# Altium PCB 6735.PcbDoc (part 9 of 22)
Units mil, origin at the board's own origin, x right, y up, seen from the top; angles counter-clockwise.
Board outline 2641.73 x 5165.35 mil, 6 copper layers (Top, Inner Layer 2, Inner Layer 3, Inner Layer 4, Inner Layer 5, Bottom), stack 35.7 mil thick; 1011 components, 790 nets, 4118 pads, 9325 vias.
Unrouted connection lines stored in the file: 4610.
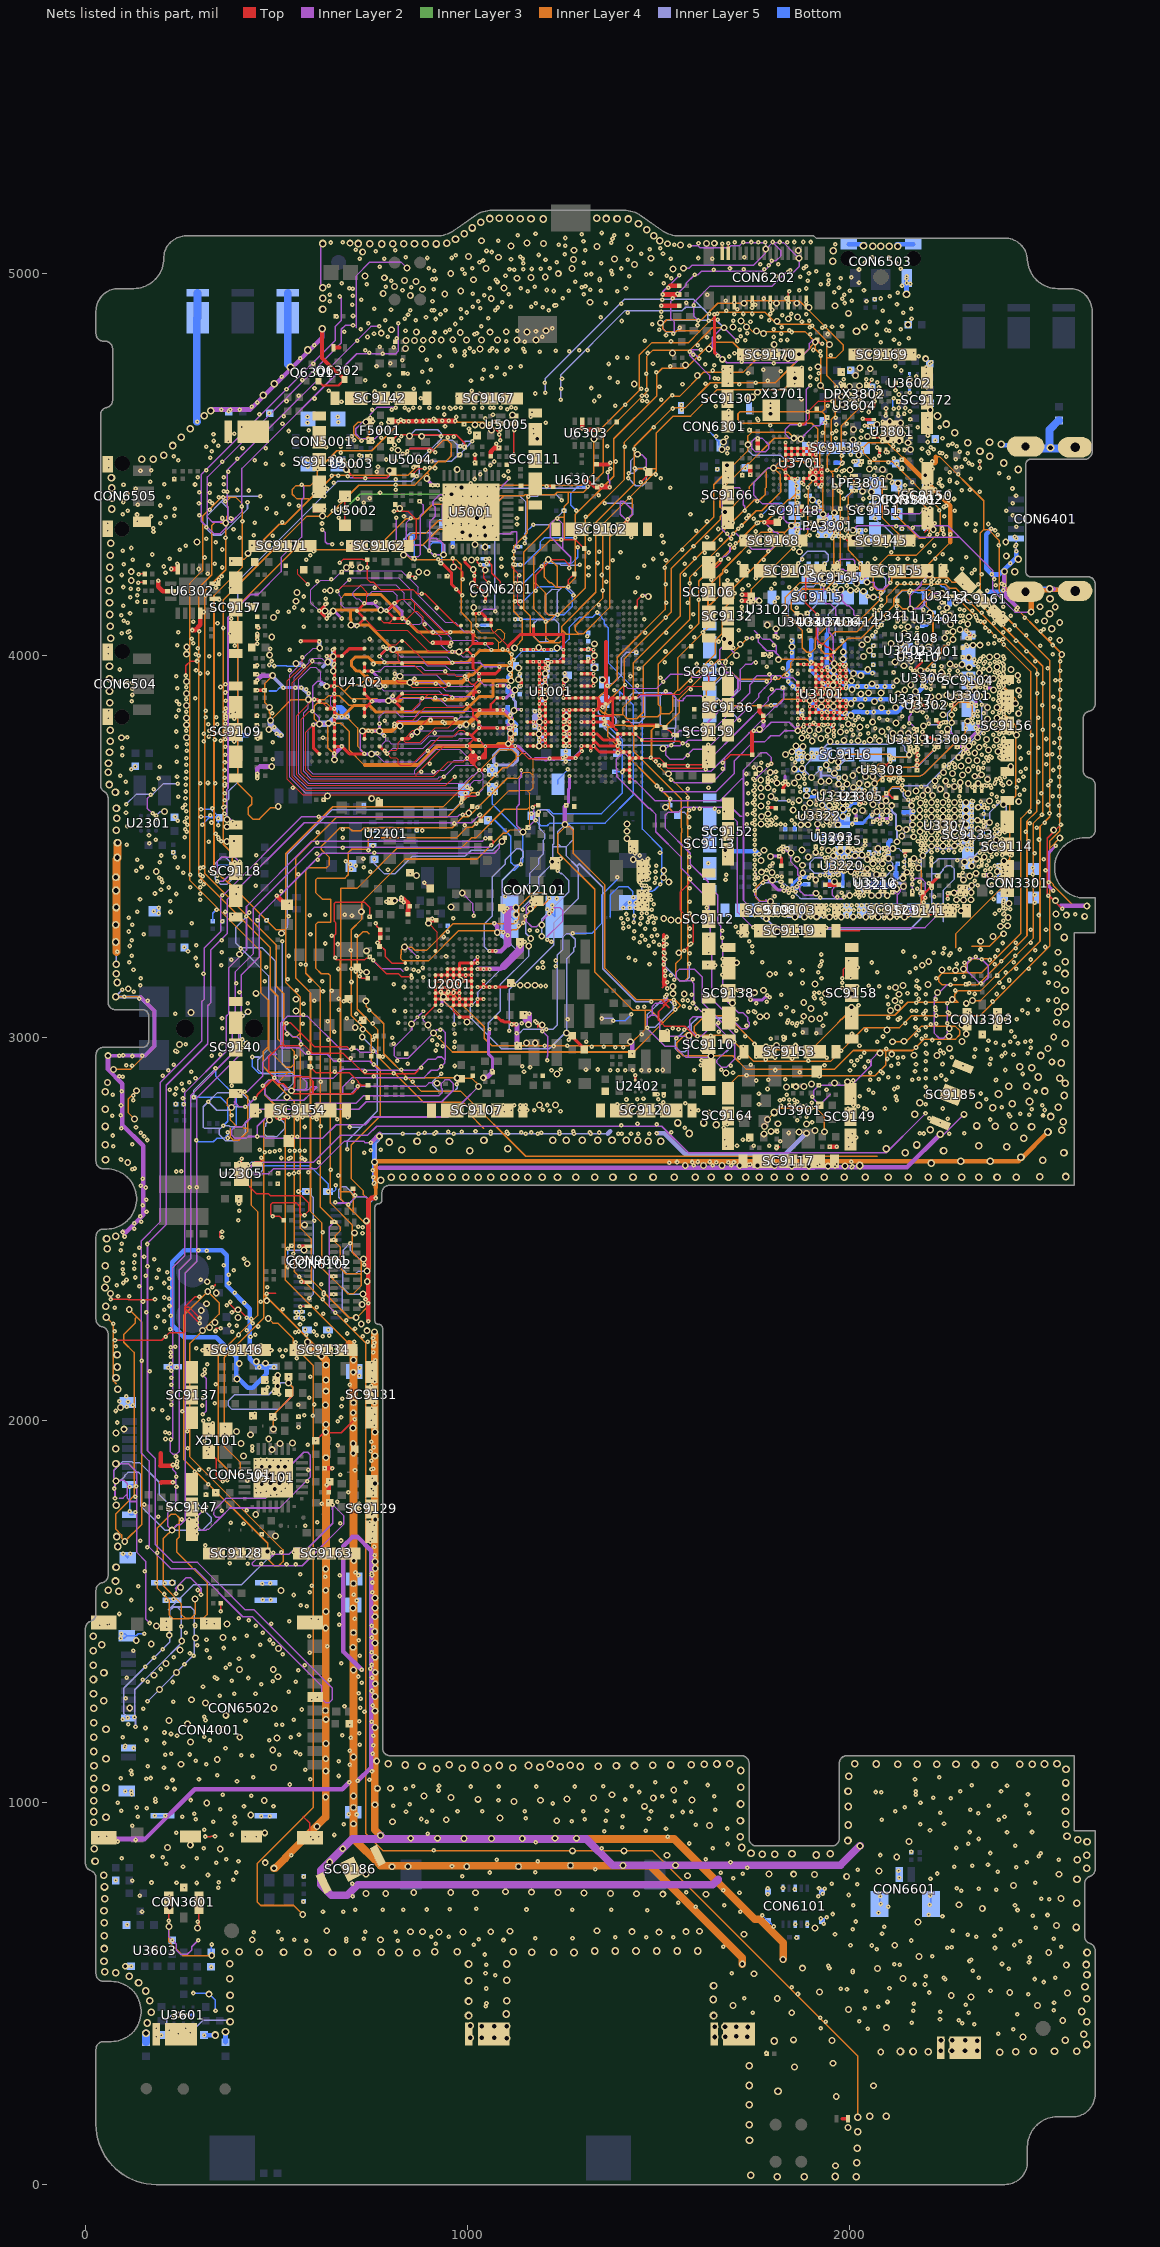
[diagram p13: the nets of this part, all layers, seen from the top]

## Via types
v1: diameter 12, hole 4, Top to Inner Layer 2, 3329 vias
v2: diameter 12, hole 4, Inner Layer 5 to Bottom, 3071 vias
v3: diameter 18, hole 10, Inner Layer 2 to Inner Layer 5, 1928 vias
v4: diameter 10, hole 4, Top to Inner Layer 2, 525 vias
v5: diameter 20, hole 12, Top to Bottom, 472 vias

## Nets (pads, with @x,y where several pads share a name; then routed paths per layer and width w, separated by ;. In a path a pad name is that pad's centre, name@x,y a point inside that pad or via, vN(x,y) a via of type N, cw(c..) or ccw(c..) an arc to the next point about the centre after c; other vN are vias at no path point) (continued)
D_GND: (continued)
  Inner Layer 4 w4: v5(54.28,2269.08) 73.26,2250.1 73.26,2102.14 80.31,2095.09 ; v3(72.95,2917.49) 117.76,2917.49 179.52,2979.25 179.52,3069.16 141.2,3107.49 85.95,3107.49 v5(79.09,3107.9) ; v3(114.62,2289.56) 134.31,2269.87 ; v3(128.44,2787.73) 112.31,2803.86 112.31,2840.84 v3(133.26,2861.78) ; v3(218.31,675.09) 218.31,635.09 254.31,599.09 v3(330.31,599.09) ; 269.31,1885.2 261.95,1892.56 ; v3(286.72,1531.93) 286.72,1492.29 275.53,1481.09 ; 379.24,2763.16 379.24,2740.16 387.31,2732.09 401.13,2732.09 424.31,2755.27 424.31,2764.09 ; v3(381.73,2818.12) 378.28,2817.64 v3@378.53,2815.88 ; 456.31,3572.09 454.31,3572.09 ; v3(478.31,2266.09) 490.57,2253.83 503.1,2253.83 543.95,2212.98 543.95,2194.82 596.31,2142.46 596.31,986.86 449.31,839.86 449.31,739.46 458.69,730.09 544.94,730.09 v3(568.54,706.49) ; v3(489.82,3947.92) 468.81,3926.91 468.81,3877.42 v3(481.31,3864.92) 481.31,3849.02 483.95,3846.38 v3(483.95,3830.49) 538.57,3885.11 v3(583.08,3885.11) 625.58,3885.11 635.58,3895.11 664.21,3895.11 689.21,3870.11 702.7,3870.11 ; v3(491.73,1976.34) 491.73,2014.29 542.31,2064.87 542.31,2086.12 v3(530.95,2097.49) ; v3(504.31,3605.09) 501.31,3602.09 484.31,3602.09 454.31,3572.09 ; v3(538.86,2861.66) 546.31,2869.11 546.31,2910.09 ; v3(581.31,2204.09) 581.31,2214.3 466.31,2329.3 ; v3(612.08,3821.11) 598.08,3835.11 598.08,3867.91 606.28,3876.11 630.35,3876.11 661.12,3845.33 677.93,3845.33 712.09,3811.16 712.09,3763.63 732.61,3743.11 v3(748.08,3743.11) ; v3(631.08,3920.11) 663.35,3920.11 677.06,3906.4 ; v3(651.27,3727.69) 651.27,3742.06 633.95,3759.38 633.95,3820.98 v3(636.08,3823.11) 668.84,3823.11 678.32,3813.63 ; 678.36,3813.63 689.98,3802.01 689.98,3752.95 729.04,3713.89 730.78,3713.89 ; 690.31,2199.09 522.31,2367.09 522.31,2792.79 502.02,2813.09 ; v3(733.91,4611.3) 742.31,4602.9 742.31,4577.04 733.36,4568.09 713.62,4568.09 701.95,4579.76 701.95,4599.49 713.28,4610.81 728.56,4610.81 732.33,4608.61 740.5,4603.83 ; v3(734.31,3096.09) 734.31,3083.01 780.31,3037.01 780.31,2958.65 844.88,2894.09 ; v3(737.3,2363.09) 737.3,2295.87 714.1,2272.68 706.14,2272.68 704.93,2271.47 v3(708.31,2268.09) 689.89,2268.09 664.04,2293.94 590.31,2367.67 590.31,2474.43 562.31,2502.43 562.31,3017.47 561.95,3017.83 ; 737.73,3944.34 737.73,3942.95 719.07,3924.3 694.96,3924.3 677.06,3906.4 ; 741.95,3272.66 736.78,3277.83 725.84,3277.83 711.31,3263.3 711.31,3074.72 764.31,3021.72 764.31,2952.02 884.39,2831.94 987.6,2831.94 1004.47,2815.07 1004.47,2800.57 1041.95,2763.09 ; 743.3,2490.09 743.3,2503.09 703.56,2542.83 ; 743.3,2574.03 727.31,2590.01 727.31,2599.72 694.84,2632.19 694.84,2719.4 771.31,2795.87 771.31,2916.44 748.31,2939.44 748.31,3005.81 695.31,3058.81 695.31,3282.87 722.31,3309.87 722.31,3354.61 835.79,3468.09 1024.85,3468.09 1091.85,3535.09 1100.67,3535.09 1108.91,3543.33 ; v3(793.08,3882.11) 767.18,3882.11 762.01,3887.27 696.18,3887.27 677.06,3906.4 ; v3(822.35,4385.09) 823.95,4386.69 v3@828.08,4386.69 ; v3(893.15,4463.49) 897.94,4474.34 894.42,4478.76 890.75,4475.84 ; v3(910.31,3013.09) 960.27,2963.13 1434.35,2963.13 1511.31,3040.09 ; 954.31,4520.87 957.31,4523.87 ; v3@969.57,2895.83 846.62,2895.83 844.88,2894.09 ; v3(972.54,2895.04) 1010.36,2895.04 1029.31,2876.09 1028.64,2873.42 1028.57,2873.05 v3(1028.62,2872.67) ; v3(984.13,4440.49) 984.31,4440.3 984.31,4405.09 975.31,4396.09 908.77,4396.09 870.75,4358.07 838.78,4358.07 774.8,4294.09 757.55,4276.83 544.97,4276.83 398.31,4130.18 398.31,3665.81 434.95,3629.17 434.95,3611.59 425.45,3602.09 425.45,3585.29 438.65,3572.09 454.31,3572.09 ; v3(997.95,3041.83) 958.69,3081.09 952.31,3081.09 936.9,3096.5 v3(936.9,3107.5) 942.49,3113.09 963.66,3113.09 976.18,3100.56 976.18,3095.17 994.39,3076.96 995.35,3076.96 1043.31,3029 1043.31,2999.28 1062.76,2979.83 1421.27,2979.83 1464.95,3023.51 1464.95,3071.45 1464.31,3072.09 ; 1008.95,4061.49 1009.29,4061.83 1009.29,4087.16 982.95,4113.5 982.95,4238.24 969.7,4251.49 851.79,4251.49 834.6,4268.68 834.6,4283.49 843.6,4292.49 851.43,4292.49 ; v3(1061.95,4590.49) 1041.35,4611.09 824.31,4611.09 749.31,4536.09 657.51,4536.09 606.31,4484.89 606.31,4462.68 588.72,4445.09 551,4445.09 540.95,4435.04 540.95,4422.62 552.48,4411.09 582.71,4411.09 585.71,4408.09 ; 1121.69,3679.46 1103.31,3679.46 1007.45,3583.6 1001.95,3578.11 987.39,3578.11 959.39,3550.11 729.33,3550.11 721.21,3541.99 697.95,3541.99 689.83,3550.11 666.09,3550.11 617.09,3501.1 617.09,3493.11 638.34,3471.85 638.34,3452.59 630.86,3445.11 581.56,3445.11 576.08,3439.63 576.08,3169.08 614.81,3130.35 614.81,2557.14 667.08,2504.87 667.08,2496.36 653.08,2482.36 653.08,2466.11 667.08,2452.11 667.08,2397.09 681.07,2383.11 718.08,2383.11 722.08,2379.11 ; v3(1122.95,4020.49) 1135.73,4033.27 1135.73,4035.07 1142.31,4041.66 1142.31,4094.09 1120.31,4116.09 1120.31,4285.51 1155.31,4320.51 1155.31,4421.09 ; 1135.3,3647.09 1108.07,3647.09 1012.12,3551.14 998.13,3551.14 970.08,3523.09 742.08,3523.09 739.58,3520.59 739.58,3495.61 737.58,3493.61 696.58,3493.61 687.8,3484.83 687.8,3426.83 679.08,3418.11 607.31,3418.11 602.08,3412.88 602.08,3380.36 619.33,3363.11 623.88,3363.11 624.08,3363.31 641.8,3363.31 641.8,3303.11 640.8,3302.11 607.56,3302.11 602.08,3296.63 602.08,3182.83 616.82,3168.09 635.31,3168.09 640.81,3162.59 640.81,2568.09 698.08,2510.82 698.08,2439.11 722.08,2415.11 722.08,2379.11 ; 1155.51,3598.09 1095.84,3598.09 1020.84,3523.09 1009.58,3523.09 983.08,3496.59 884.08,3496.59 883.6,3496.11 815.16,3496.11 710.16,3391.11 668.3,3391.11 668.3,3206.09 667.3,3205.09 667.3,2597.11 668.3,2596.11 ; v3(1210.95,4251.83) 1212.17,4253.05 1220.44,4244.78 1222.27,4244.78 1223.78,4243.27 1224.25,4243.27 1225.08,4242.43 1225.56,4242.43 1234.08,4233.91 1234.08,4233.09 ; v3@1211.74,4255.49 1200.08,4243.83 1200.08,4205.89 1203.43,4202.54 1203.43,4202.14 1214.74,4190.83 1219.09,4190.83 1230.93,4178.99 1235.08,4178.99 ; 1234.14,4233.09 1234.08,4233.09 ; 1244.08,4038.09 1239.82,4033.83 1189.39,4033.83 1163.81,4059.41 1163.81,4103.57 1147.3,4120.09 1147.3,4272.08 1211.95,4336.73 1211.95,4340.04 1234.39,4362.49 1253.03,4362.49 1253.3,4362.22 ; 1451.53,3840.09 1497.31,3840.09 1505.31,3848.09 ; 1629.31,4133.09 1634.43,4133.09 1659.89,4158.55 1659.89,4207.69 1667.31,4215.11 ; 1638.31,2968.7 1638.31,2955.09 v3(1636.31,2953.09) ; v3(1670.31,4858.09) 1640.03,4858.09 1581.43,4799.49 1484.71,4799.49 1467.95,4782.73 1467.95,4690 1355.31,4577.36 1355.31,4480.25 1302.77,4427.7 1263.3,4427.7 ; 1671.5,2864.56 1708.5,2901.56 2066.28,2901.56 2093.64,2928.93 2093.64,2967.09 ; v3(1714.95,4875.49) 1717.9,4875.49 1745.3,4848.09 1882.3,4848.09 v3(1909.3,4821.09) ; 1729.95,4043.76 1676.02,3989.83 1656.42,3989.83 1552.95,3886.36 1552.95,3850.7 1519.08,3816.83 1492.83,3816.83 1492.09,3816.09 ; 1742.54,4148.37 1742.54,4174.52 1890.31,4322.29 1890.31,4343.09 ; v3(1780.43,3418.88) 1753.71,3392.16 1753.71,3367.34 1764.04,3357.02 v3(1791.99,3357.02) ; v3(1784.19,2786.32) 1814.43,2816.56 1911.31,2816.56 1933.3,2794.58 v3(1933.3,2754.63) ; v3(1801.95,4814.49) 1801.95,4796.55 1781.51,4776.11 1757.3,4776.11 1756.3,4777.11 ; v3(1813.65,3989.59) 1814.62,3990.56 1853.46,3990.56 1853.86,3990.16 ; 1821.51,4489.09 1822.31,4489.09 ; 1838.83,4331.6 1830.82,4323.59 ; v3@1846.31,4569.09 1802.31,4569.09 1736.31,4503.09 1732.3,4503.09 1660.22,4431.01 1660.22,4388.92 v3(1673.31,4375.83) ; v3(1853.31,4569.09) 1853.31,4571.09 1840.31,4584.09 1742.31,4584.09 1733.31,4575.09 v3(1733.31,4552.09) 1733.31,4536.68 1643.73,4447.1 1643.73,4362.95 1516.62,4235.84 1516.62,4120.86 1391.42,3995.66 1391.42,3938.72 1351.79,3899.09 1350.95,3899.09 1340.31,3888.45 1340.31,3863.55 1354.54,3849.32 1358.08,3852.87 ; v3(1856.31,4726.09) 1825.71,4695.49 1651.4,4695.49 1583,4627.09 1538.01,4627.09 1493.31,4582.39 1493.31,4490.09 ; v3(1923.31,4345.09) 1933.14,4345.09 1933.14,4355.8 1930.31,4358.63 ; v3(1929.31,4370.09) 1929.31,4384.09 ; 1929.65,4086.09 1916.74,4086.09 v3(1916.48,4085.83) ; v3@1933.14,4204.2 v3@1932.09,4203.15 ; v3(1934.37,4203.89) v3@1932.09,4203.15 ; v3(1958.98,3979.58) 1959.2,3979.58 1959.2,3990.54 1944.65,4005.09 ; v3(1959.31,4374.09) v3@1954.65,4374.09 ; v3(1959.31,4443.09) v3@1954.65,4443.09 ; v3(1965.22,4202.59) v3@1961.65,4202.59 ; 1974.31,4232.63 1974.31,4457.34 1980.06,4463.09 2005.31,4463.09 2011.31,4457.09 2011.31,4432.63 1996.31,4417.63 1996.31,4276.09 2009.31,4263.09 2009.31,4262.09 ; v3(1992.44,3735.2) 1999.83,3742.59 2103.65,3742.59 2111.65,3734.59 2149.15,3734.59 v3(2155.25,3740.69) ; v3(2002.53,3435.36) 2004.76,3437.59 2040.65,3437.59 v3(2045.65,3442.59) ; 2005.3,4266.11 2009.31,4262.09 ; v5(2020.31,176.09) 2020.31,336.35 1483.57,873.09 v3(1409.31,873.09) v3(1274.31,873.09) 778.38,873.09 759.38,892.09 744.37,907.09 733.31,918.15 733.31,2201.75 546.31,2388.75 546.31,2833.95 507.31,2872.95 ; 2039.3,4211.09 2025.42,4224.97 2025.42,4245.99 2009.31,4262.09 ; 2053.76,4662.09 2037.76,4646.09 2022.3,4646.09 1977.31,4601.1 1977.31,4499.09 1960.31,4482.09 1949.31,4482.09 ; v3(2059.73,3683.77) 2059.73,3701.02 2075.3,3716.59 2088.29,3716.59 cw(c2088.29,3706.06) 2095.74,3713.51 2099.24,3710 ccw(c2102.65,3713.42) 2102.65,3708.59 2157.9,3708.59 ccw(c2157.9,3746.61) 2184.79,3719.73 2234.48,3769.41 v3(2234.48,3776.15) ; 2071.53,2690.3 1151.87,2690.3 982.34,2859.83 879.13,2859.83 844.88,2894.09 ; 2072.62,4170.98 2071.41,4170.98 2060.87,4181.53 2060.87,4223.2 2100.81,4263.15 2173.95,4263.15 2236.95,4326.15 2236.95,4381.56 2109.42,4509.09 2056.84,4509.09 2035.3,4530.63 2035.3,4545.54 2046.59,4556.83 2098.88,4556.83 2140.07,4515.64 ; 2072.63,4170.97 2087.54,4170.97 2087.64,4171.07 ; v3(2084.31,4464.09) 2084.31,4361.93 2155.17,4291.08 2165.82,4291.08 2165.82,4303.83 2174.95,4312.96 ; v3(2111.31,2990.09) 2146.53,2990.09 2187.53,3031.09 2275.3,3031.09 2287.3,3019.09 2287.3,3008.09 2276.3,2997.09 2194.61,2997.09 2164.61,2967.09 2093.64,2967.09 ; 2112.27,4203.65 2255.97,4203.65 2257.12,4202.5 2257.22,4202.5 2267.1,4192.62 2278.51,4192.62 2278.58,4192.54 2284.3,4192.54 2504.65,3972.19 2504.65,3585.99 2479.43,3560.77 2479.43,3260.43 2342.09,3123.09 2283.1,3123.09 2274.31,3114.3 2274.31,3101.87 2283.1,3093.09 2151.31,3093.09 2117.37,3059.14 1989.08,3059.14 1978.53,3048.59 1977.44,3048.59 1968.65,3039.8 1968.65,3038.72 1899.5,2969.56 1766.94,2969.56 1678.41,3058.09 1621.1,3058.09 1593.31,3030.3 1593.31,3015.87 1596.31,3012.87 ; 2116.06,4151 2115.79,4151.21 ; v3(2126.31,4451.09) 2126.31,4439.31 2128.31,4437.31 2128.31,4413.19 2121.95,4406.83 2121.95,4365.96 2174.95,4312.96 ; v3(2143.06,3316.61) 2153.67,3316.61 2182.41,3345.35 ; v3(2144.31,4428.09) 2159.31,4428.09 2207.95,4379.45 2207.95,4318.66 ; v3(2151.65,3639.59) 2134.65,3656.59 2110.65,3656.59 2101.65,3647.59 2101.65,3641.59 2091.65,3631.59 2069.65,3631.59 2064.65,3636.59 v3(2064.65,3665.59) 2067.65,3665.59 2086.65,3684.59 2175.83,3684.59 ; v3(2179.65,3444.59) 2186.65,3437.59 2186.65,3355.59 ; v3(2185.11,3961.17) 2185.11,3964.31 2197.83,3964.31 2239.48,4005.96 2239.48,4018.41 2246.97,4025.89 2252.63,4025.89 2269.49,4042.75 2270.07,4043.33 v3(2270.07,4063.34) ; v3(2205.91,4023.3) 2217.48,4034.87 2217.48,4112.63 2200.31,4129.8 2200.31,4151.79 ; 2207.95,4317.83 2207.95,4318.66 ; 2224.3,4520.11 2235.7,4520.11 2350.1,4405.7 2350.1,4330.09 ; 2262.95,4297.15 2203.45,4237.65 2123.1,4237.65 2109.31,4223.86 2109.31,4192.71 2087.67,4171.07 ; v3(2266.65,3824.59) v3(2266.65,3845.59) 2266.65,3860.59 2284.65,3878.59 2305.65,3878.59 ; 2277.5,3235.54 2277.5,3273.1 2421.65,3417.25 2417.72,3421.18 2417.72,3467.96 ; v3@2305.65,3831.59 2307.32,3829.93 v3(2307.32,3828.49) ; 2319.14,3239.92 2365.27,3239.92 2400.12,3274.77 2402.4,3277.04 v3(2402.4,3272.49) ; v3(2321.16,3097.62) 2342.08,3097.62 2497.43,3252.97 2497.43,3553.31 2522.65,3578.53 2522.65,3987.17 2341.31,4168.51 2341.31,4321.3 2350.1,4330.09 ; 2371.31,3207.09 2320.86,3207.09 2303.31,3189.54 2303.31,3170.09 ; v3@2383.31,3868.09 2414.31,3837.09 ; 2401.2,3920.09 2433.37,3887.92 v3(2433.37,3874.93) ; 2414.36,3837.04 2434.54,3816.86 2434.54,3633.65 2417.72,3616.83 2417.72,3467.96 ; v3(2415.74,3412.82) 2415.74,3465.98 2417.72,3467.96 ; 2447.41,3373.08 2447.41,3430.68 2447.4,3574.08 2472.65,3599.33 2472.65,3958.93 2274.93,4156.65 2247.81,4156.65 2241.01,4163.45 v3(2241.06,4163.5) 2240.81,4163.65 2217.81,4163.65 2213.81,4167.65 ; 2447.43,3373.06 2447.43,3273.68 2343.84,3170.09 2303.31,3170.09 ; 2463.41,3379.73 2463.41,3448.17 2463.4,3567.36 2488.65,3592.61 2488.65,3965.56 2277.67,4176.54 2260.55,4176.54 2250.59,4186.5 2250.49,4186.5 2249.49,4187.5 2129.45,4187.5 2097.06,4155.11 2097.06,4140.61 2018.95,4062.5 1961.06,4062.5 1925.36,4026.8 1925.36,4014.22 1934.5,4005.09 1944.65,4005.09 ; 2463.43,3379.71 2463.43,3267.06 2335.47,3139.09 2241.1,3139.09 2232.31,3147.88 2232.31,3160.3 2241.1,3169.09 2297.31,3169.09 2298.31,3170.09 2303.31,3170.09 ; v3(2549.3,3523.09) 2523.43,3497.22 ; v3(2619.95,3345.49) 2585.24,3345.49 2531.55,3399.18 2531.55,3402.38 2523.43,3410.5 ; 134.31,2269.87 130.31,2265.87 130.31,2253.88 100.31,2223.88 100.31,2204.02 127.31,2177.02 127.31,1802.16 79.31,1754.16 79.31,1714.82 94.47,1699.66 94.47,1691.32 v3(102.95,1682.83) 147.31,1727.19 147.31,2256.87 134.31,2269.87 ; 245.31,1731.09 v3(226.31,1712.09) 217.69,1703.47 216.48,1703.47 203.31,1690.3 203.31,1567.09 250.31,1520.09 250.31,1493.09 262.31,1481.09 271.31,1481.09 ; 245.31,1731.09 245.31,1694.3 239.31,1688.3 239.31,1654.41 318.31,1575.41 318.31,1491.27 308.14,1481.09 275.53,1481.09 ; 245.31,1731.09 245.31,1744.68 235.9,1754.09 224.31,1754.09 187.31,1717.09 187.31,1560.46 219.31,1528.46 219.31,1489.88 229.1,1480.09 270.31,1480.09 271.31,1481.09 ; 261.95,1892.56 476.95,1677.56 476.95,1636.3 494.42,1618.83 505.84,1618.83 516.95,1629.94 516.95,1660.18 273.31,1903.82 273.31,2201.09 349.74,2277.52 349.74,2307.04 v3(319.95,2336.83) 257.31,2274.19 257.31,1897.2 261.95,1892.56 ; 271.31,1481.09 275.53,1481.09 ; v3(366.95,4346.83) 355.56,4346.83 352.56,4349.83 339.74,4349.83 330.63,4340.72 330.63,4211.91 296.31,4177.59 296.31,3423.58 483.31,3236.58 483.31,3128.72 503.31,3108.72 503.31,2997.26 525.74,2974.83 536.17,2974.83 545.95,2965.04 ; v3(366.95,4346.83) 366.95,4224.7 312.31,4170.06 312.31,3430.29 499.31,3243.29 499.31,3135.37 519.31,3115.37 519.31,3025.26 542.42,3002.15 551.48,3002.15 561.95,3012.62 561.95,3017.83 ; v3(366.95,4346.83) 368.95,4344.83 369.31,4345.09 369.31,4363.48 372.31,4366.48 372.31,4389.59 371.31,4390.59 371.31,4406.3 380.1,4415.09 ; 371.1,3408.09 361.36,3417.83 358.74,3417.83 336.31,3440.26 336.31,4157.82 410.73,4232.24 410.73,4251.86 ; 371.1,3408.09 374.99,3404.2 377.24,3404.2 493.31,3288.12 498.34,3283.09 523.08,3283.09 524.08,3284.09 ; 371.1,3408.09 384.31,3421.3 384.31,3482.58 360.31,3506.58 360.31,4145.92 441.66,4227.26 579.77,4365.37 v3(620.21,4365.37) 632.31,4363.22 715.18,4446.09 861,4446.09 889.74,4474.83 ; v3@378.53,2815.88 v3@379.24,2810.7 ; v3@378.53,2815.88 371.31,2823.09 371.31,2840.09 388.31,2857.09 413.31,2857.09 424.31,2846.09 424.31,2764.09 ; v3@378.53,2815.88 379.31,2815.09 379.31,2810.7 v3@379.24,2810.7 ; v3@379.24,2810.7 379.24,2784.94 397.09,2767.09 410.72,2767.09 413.72,2764.09 424.31,2764.09 ; 380.1,4415.09 356.69,4415.09 306.31,4364.72 306.31,4222.71 272.31,4188.71 272.31,3413.25 458.31,3227.25 458.31,3119.09 478.93,3098.47 478.93,2978.09 ; 380.1,4415.09 392.53,4415.09 410.73,4396.88 410.73,4251.86 ; 410.73,4251.86 414.73,4251.86 506.9,4344.03 521.65,4344.03 585.71,4408.09 ; 465.95,2681.83 465.95,2785.27 493.78,2813.09 502.02,2813.09 ; 465.95,2681.83 466.31,2681.47 466.31,2329.3 ; 465.95,2681.83 460.21,2676.09 443.33,2676.09 433.31,2666.07 433.31,2562.54 450.31,2545.54 450.31,2273.72 347.31,2170.72 347.31,1894.88 384.1,1858.09 396.53,1858.09 405.31,1866.88 405.31,1889.28 363.31,1931.28 363.31,2164.09 466.31,2267.09 466.31,2312.55 466.31,2329.3 ; 478.93,2978.09 464.98,2964.13 464.98,2924.87 479.76,2910.09 530,2910.09 ; 478.93,2978.09 478.93,2968.64 524.74,2922.83 537.17,2922.83 545.95,2931.62 545.95,2965.04 ; 502.02,2813.09 502.02,2818.38 469.31,2851.09 469.31,2879.66 478.75,2889.09 491.17,2889.09 507.31,2872.95 ; 507.31,2872.95 507.31,2887.4 530,2910.09 ; 524.08,3284.09 524.08,3481.64 647.27,3604.83 790.95,3604.83 791.29,3604.49 935.74,3604.49 1085.74,3754.49 1114.95,3754.49 1126.95,3742.49 1126.95,3736.53 1126.95,3730.91 1102.93,3706.89 1091.85,3706.89 1026.79,3641.83 1010.45,3641.83 945.95,3577.33 656.54,3577.33 550.08,3470.87 550.08,3156.62 588.8,3117.9 588.8,2545.95 617.86,2516.89 617.86,2398.67 685.44,2331.09 701.3,2331.09 722.08,2351.87 722.08,2379.11 ; 524.08,3284.09 524.08,3144.63 561.95,3106.76 561.95,3017.83 ; 530,2910.09 546.31,2910.09 ; 545.95,2965.04 546.31,2964.68 546.31,2910.09 ; 585.71,4408.09 649.71,4472.09 844.21,4472.09 935.21,4563.09 947.89,4563.09 957.31,4553.67 957.31,4523.87 ; 668.3,2596.11 670.3,2598.11 690.49,2598.11 700.3,2588.3 700.3,2546.09 703.56,2542.83 ; 668.31,2596.1 668.31,2577.87 703.35,2542.83 703.56,2542.83 ; 851.43,4292.49 854.83,4289.09 882.04,4289.09 924.04,4331.09 1027.72,4331.09 1066.31,4369.69 1066.31,4390.3 ; 851.43,4292.49 845.31,4298.61 845.31,4310.86 854.52,4320.07 889.71,4320.07 922.74,4353.09 987.31,4353.09 1080.31,4446.09 1297.53,4446.09 1329.31,4477.88 1329.31,4574.04 1448.42,4693.15 1448.42,4785.82 1481.04,4818.44 1577.16,4818.44 1606.81,4848.09 ; 889.74,4474.83 889.74,4475.04 890.75,4475.84 ; 889.74,4474.83 890.75,4475.84 ; 890.75,4475.84 923,4508.09 942.79,4508.09 957.31,4522.62 957.31,4523.87 ; 1066.31,4390.3 1094.1,4418.09 ; 1066.31,4390.3 1066.31,4401.17 1083.24,4418.09 1094.1,4418.09 ; 1094.1,4418.09 1147.55,4418.09 1150.55,4421.09 1155.31,4421.09 ; 1155.31,4421.09 1227.67,4421.09 1234.29,4427.7 1263.3,4427.7 ; 1173.3,4190.11 1173.3,4259.83 1215.58,4302.11 1248.08,4302.11 1253.3,4307.33 1253.3,4362.22 ; 1173.3,4190.11 1177.3,4190.11 1203.62,4163.79 1203.62,4115.09 1212.62,4106.09 1228.34,4106.09 ; 1173.3,4190.11 1173.3,4122.29 1201.5,4094.09 1203.95,4094.09 1203.95,4081.7 ; 1203.95,4081.7 1228.34,4106.09 ; 1203.95,4081.7 1203.95,4048.27 1213.74,4038.49 1226.16,4038.49 1245.88,4058.2 1245.88,4067.89 ; 1228.34,4106.09 1230.74,4108.49 1238.67,4108.49 1307.51,4177.33 1307.51,4358.41 1409.08,4459.98 1409.08,4557.55 1530.01,4678.49 1554.05,4678.49 1616.65,4741.09 1720.28,4741.09 1756.3,4777.11 ; 1234.08,4233.09 1234.08,4179.99 1235.08,4178.99 ; 1235.08,4178.99 1235.24,4178.83 1257.16,4178.83 1280.89,4202.56 1280.89,4368.58 1382.09,4469.78 1382.09,4567.34 1494.45,4679.7 1494.45,4737.73 1508.8,4752.08 1571.12,4752.08 1639.15,4820.11 1693.49,4820.11 1733.06,4780.54 1752.87,4780.54 1756.3,4777.11 ; 1245.88,4067.89 1257.94,4055.83 1289.36,4055.83 1290.36,4056.83 ; 1245.88,4067.89 1245.88,4076.41 1335.31,4165.85 1335.31,4348.2 1436.08,4448.96 1436.08,4489.09 ; 1253.3,4362.22 1253.3,4391.02 1263.3,4401.02 1263.3,4427.7 ; 1290.36,4056.83 1302.27,4056.83 1371.31,4125.88 1371.31,4309.63 1430.31,4368.63 1430.31,4409.73 1424.95,4415.09 ; 1290.36,4056.83 1281.31,4065.87 1281.31,4078.3 1352.95,4149.94 1352.95,4343.09 1424.95,4415.09 ; 1358.08,3852.87 1360.3,3855.09 ; 1358.08,3852.87 1358.08,3822.89 1366.87,3814.11 1367.08,3814.11 ; 1360.3,3855.09 1360.3,3850.87 1365.08,3846.09 1406.3,3846.09 ; 1360.3,3855.09 1362.08,3856.87 1362.08,3867.76 1362.96,3868.64 1363.31,3868.64 1377.13,3882.46 1377.13,3890.74 1409.36,3922.97 1409.36,3990.95 1532.67,4114.25 1532.67,4227.8 1660.89,4356.02 1660.89,4363.4 v3(1673.31,4375.83) ; 1367.08,3814.11 1367.08,3788.59 1527.31,3628.36 1527.31,3600.82 1538.04,3590.09 1550.47,3590.09 1559.15,3598.78 ; 1367.08,3814.11 1367.7,3813.49 1381.21,3813.49 1385.21,3817.49 1413.95,3817.49 1415.35,3816.09 1433.95,3816.09 ; 1406.3,3846.09 1406.3,3864.4 1433.48,3891.57 1433.48,3981.05 1556.67,4104.23 1556.67,4214.48 1750.17,4407.98 1764.42,4407.98 1779.14,4422.7 1779.14,4438.42 1781.31,4440.6 1781.31,4480.96 1778.64,4483.63 ; 1406.3,3846.09 1417.3,3835.09 1442.53,3835.09 1459.46,3852.02 1459.46,3972.97 1580.67,4094.18 1580.67,4204.54 1755.25,4379.12 1769.5,4379.12 1819.57,4429.2 1819.57,4451.73 1817.58,4453.72 1817.58,4473.82 v3(1800.31,4491.09) ; 1424.95,4415.09 1493.31,4483.45 1493.31,4490.09 ; 1433.95,3816.09 1433.95,3749.84 1559.31,3624.47 1559.31,3598.94 1559.15,3598.78 ; 1433.95,3816.09 1492.09,3816.09 ; 1436.08,4489.09 1492.31,4489.09 1493.31,4490.09 ; 1436.08,4489.09 1436.08,4547.78 1537.39,4649.09 1569.61,4649.09 1634.61,4714.09 1804.53,4714.09 1897.42,4806.98 1897.42,4809.2 v3(1909.3,4821.09) ; 1464.31,3072.09 1479.31,3072.09 1511.31,3040.09 ; 1464.31,3072.09 1432.7,3072.09 1332.31,3172.48 1332.31,3388.87 1235.95,3485.23 1235.95,3533.3 1254.74,3552.09 1267.17,3552.09 1275.95,3543.3 1275.95,3525.49 1275.7,3525.24 1275.7,3483.07 1358.95,3399.82 1358.95,3182.61 1441.73,3099.83 1492.05,3099.83 1492.31,3100.09 1542.31,3100.09 1556.81,3085.59 1511.31,3040.09 ; 1492.09,3816.09 1480.95,3804.95 1480.95,3729.86 1575.31,3635.5 1575.31,3588.85 1575.15,3588.69 1575.15,3556.05 1575.56,3555.64 1575.56,3529.96 1575.31,3529.71 1575.31,3157.09 1567.31,3149.09 1554.58,3149.09 1544.08,3159.59 1544.08,3193.86 1559.31,3209.09 1559.31,3509.43 1559.15,3509.59 1559.15,3536.18 1559.56,3536.59 1559.56,3549.02 1559.15,3549.43 1559.15,3598.78 ; 1505.31,3848.09 1527.71,3848.09 1536.31,3856.69 1536.31,3897.15 1549.31,3910.15 ; 1505.31,3848.09 1505.31,3866.04 1498.31,3873.04 1498.31,3977.76 1604.67,4084.11 1604.67,4194.6 1761.75,4351.68 1781.46,4351.68 1837.86,4408.09 1843.53,4408.09 1857.31,4421.87 ; 1549.31,3910.15 1553.31,3910.15 1647.95,4004.79 1647.95,4039.93 1665.95,4057.93 1665.95,4119.36 1695.95,4149.36 1695.95,4178.57 1828.43,4311.05 1828.43,4321.2 1830.82,4323.59 ; 1549.31,3910.15 1549.31,3994.06 1628.8,4073.55 1628.8,4180.6 1663.31,4215.11 1667.31,4215.11 ; 1596.31,3012.87 1602.1,3007.09 1679.71,3007.09 1748.24,2938.56 1949.14,2938.56 2037.67,3027.09 2129.98,3027.09 2160.98,3058.09 2340.3,3058.09 2523.43,3241.22 2523.43,3410.5 ; 1596.31,3012.87 1573.08,3012.87 1554.3,2994.09 1553.82,2994.09 1547.3,2987.57 1547.3,2970.1 1564.31,2953.09 v3(1636.31,2953.09) ; 1606.81,4848.09 1604.81,4850.09 1547.31,4850.09 1544.31,4847.09 1519.1,4847.09 1510.31,4855.87 1510.31,4868.3 1521.1,4879.09 1611.49,4879.09 1654.49,4922.09 v3(1723.31,4922.09) 1730.31,4929.09 1866.91,4929.09 1867.42,4928.58 1889.06,4906.94 1982.31,4813.68 1982.31,4798.87 1963.53,4780.09 1939.31,4780.09 ; 1606.81,4848.09 1657.21,4898.49 1777.81,4898.49 1809.21,4867.09 1895.83,4867.09 1939.31,4823.6 1939.31,4814.02 1939.31,4780.09 ; v3(1636.31,2953.09) 1664.28,2953.09 1664.58,2953.39 1676.99,2953.39 1677.29,2953.09 1693.7,2953.09 1728.23,2918.56 1960.53,2918.56 2009.06,2967.09 2093.64,2967.09 ; 1667.31,4215.11 1667.31,4223.3 1767.6,4323.59 1830.82,4323.59 ; v3(1673.31,4375.83) 1681.09,4383.61 1681.61,4383.09 1686.79,4383.09 1699.31,4395.62 1699.31,4396.75 1736.31,4433.75 1736.31,4441.3 1778.64,4483.63 ; 1778.64,4483.63 1786.1,4491.09 v3(1800.31,4491.09) ; v3(1800.31,4491.09) 1818.31,4509.09 1875.51,4509.09 1899.31,4485.29 1899.31,4469.07 v3@1900.31,4468.07 ; v3(1800.31,4491.09) 1820.31,4491.09 1822.31,4489.09 ; 1822.31,4489.09 1858.31,4453.09 1858.31,4422.87 1857.31,4421.87 ; 1830.82,4323.59 v3(1847.31,4340.09) 1857.31,4350.09 1857.31,4421.87 ; 1853.86,3990.16 1854.11,3990.16 1854.6,3990.65 1886.9,3990.65 1894.01,3983.54 1905.48,3983.54 1927.68,3961.35 1927.68,3920.38 1925.65,3918.35 v3(1925.65,3903.59) 1920.65,3898.59 v3(1879.15,3898.59) 1867.14,3886.58 1824.13,3886.58 1806.96,3869.41 1661.86,3869.41 1651.56,3879.71 1639.32,3879.71 1624.15,3894.88 1624.15,3909.8 1670.44,3956.09 1691.84,3956.09 1709.84,3938.09 1814.61,3938.09 1845.89,3969.36 1845.81,3969.44 1845.81,3981.86 1846.01,3982.06 1846.01,3982.3 1853.86,3990.16 ; 1890.31,4343.09 1914.77,4343.09 1930.31,4358.63 ; 1890.31,4343.09 1890.31,4385.22 1891.31,4386.22 ; 1891.31,4386.22 1927.18,4386.22 1929.31,4384.09 ; 1891.31,4386.22 1891.31,4445.59 1900.31,4454.59 v3@1900.31,4468.07 ; v3@1900.31,4468.07 v3(1903.31,4465.09) v3@1900.31,4468.07 ; v3@1900.31,4468.07 1900.31,4547.85 1916.31,4563.85 1916.31,4592.3 1900.52,4608.09 1716.09,4608.09 1707.31,4616.87 1707.31,4632.76 1712.64,4638.09 1927.31,4638.09 ; v3(1909.3,4821.09) 1909.3,4802.1 1923.31,4788.09 v3(1923.31,4707.09) 1934.31,4696.09 1934.31,4645.09 1927.31,4638.09 ; v3(1916.48,4085.83) 1916.48,4086.09 1882.52,4086.09 1847.1,4121.51 1847.1,4145.83 1875.82,4174.55 1890.15,4174.55 1891.36,4173.33 1936.97,4173.33 1958.22,4194.58 1958.22,4197.63 1962.42,4201.83 v3@1961.65,4202.59 ; v3(1916.48,4085.83) 1916.48,4063.76 1921.65,4058.59 ; 1921.65,4058.59 1908.87,4045.81 1908.87,4018.09 1899.59,4008.8 1887.16,4008.8 1875.4,4020.56 1875.4,4066.09 1831.18,4110.32 1831.18,4117.06 1831.1,4117.14 1831.1,4152.46 1851.03,4172.39 1851.03,4173.08 1868.5,4190.55 1901.79,4190.55 1903.01,4189.33 1918.28,4189.33 v3@1932.09,4203.15 ; 1921.65,4058.59 1945.06,4082 2014.52,4082 2077.75,4145.23 2077.75,4158.97 2087.67,4168.89 2087.67,4171.07 ; 1927.31,4638.09 1934.31,4631.09 1934.31,4550.03 1921.31,4537.03 1921.31,4485.05 1929.31,4477.05 1929.31,4384.09 ; 1929.31,4384.09 1930.31,4383.09 1930.31,4358.63 ; 1939.31,4780.09 1939.31,4732.75 1962.31,4709.75 v3(1962.31,4646.09) 1962.31,4628.93 1951.81,4618.43 1951.81,4534.02 1940.31,4522.52 1940.31,4491.09 1949.31,4482.09 ; 1944.65,4005.09 1954.01,4005.09 1994.18,4045.26 2028.56,4045.26 2115.31,4132.01 2115.31,4150.73 2115.75,4151.17 ; 1949.31,4482.09 1954.65,4476.75 v3@1954.65,4443.09 ; v3@1954.65,4374.09 1954.65,4362.89 1958.22,4359.32 1958.22,4202.59 v3@1961.65,4202.59 ; v3@1954.65,4374.09 v3@1954.65,4443.09 ; 2115.75,4151.17 2119.23,4147.68 2119.23,4141.78 2137.98,4123.03 v3@2158.31,4123.03 ; 2115.75,4151.17 2115.79,4151.21 ; 2115.79,4151.21 2136.08,4171.5 2156.31,4171.5 ; 2156.31,4171.5 2156.31,4151.84 2158.31,4149.84 v3@2158.31,4123.03 ; 2156.31,4171.5 2209.96,4171.5 2213.81,4167.65 ; v3@2158.31,4123.03 v3(2158.56,4122.5) 2158.56,4123.03 2171.54,4123.03 2200.31,4151.79 ; 2174.95,4312.96 2181.08,4306.83 2196.12,4306.83 2207.95,4318.66 ; 2175.83,3684.59 ccw(c2175.83,3713.12) 2196.01,3692.95 ; 2175.83,3684.59 ccw(c2175.83,3713.12) 2196.01,3692.95 ; 2175.83,3684.59 ccw(c2175.83,3713.12) 2196.01,3692.95 ; 2175.83,3684.59 ccw(c2175.83,3713.12) 2196.01,3692.95 ; 2182.41,3345.35 ccw(c2172.17,3355.59) 2186.65,3355.59 ; 2182.41,3345.35 ccw(c2172.17,3355.59) 2186.65,3355.59 ; 2182.41,3345.35 ccw(c2172.17,3355.59) 2186.65,3355.59 ; 2182.41,3345.35 ccw(c2172.17,3355.59) 2186.65,3355.59 ; 2182.41,3345.35 ccw(c2172.17,3355.59) 2186.65,3355.59 ; 2182.41,3345.35 ccw(c2172.17,3355.59) 2186.65,3355.59 ; 2182.41,3345.35 ccw(c2172.17,3355.59) 2186.65,3355.59 ; 2182.41,3345.35 ccw(c2172.17,3355.59) 2186.65,3355.59 ; 2182.41,3345.35 ccw(c2172.17,3355.59) 2186.65,3355.59 ; 2196.01,3692.95 2301.65,3798.59 2301.65,3822.83 v3(2307.32,3828.49) ; 2200.31,4151.79 2202.82,4154.3 2202.82,4156.66 2213.81,4167.65 ; 2305.65,3878.59 cw(c2305.65,3868.93) 2312.48,3875.76 ; 2305.65,3878.59 cw(c2305.65,3868.93) 2312.48,3875.76 ; v3(2307.32,3828.49) 2320.65,3841.83 2320.65,3867.59 2312.48,3875.76 ; 2350.1,4330.09 2362.53,4330.09 2390.31,4302.3 2390.31,4169.5 2549.31,4010.5 2549.31,3541.44 2523.43,3515.56 2523.43,3497.22 ; 2523.43,3410.5 2523.43,3497.22 ; 825.31,3206.63 830.45,3201.49 897.19,3201.49 976.53,3280.83 1114.5,3280.83 1116.5,3282.83 1127.58,3282.83 1149.95,3305.2 1149.95,3316.28 1180.5,3346.83 1197.17,3346.83 1208.95,3358.62 1208.95,3371.04 1200.17,3379.83 1169.43,3379.83 1133.95,3344.35 1133.95,3311.83 1120.95,3298.83 961.96,3298.83 891.96,3228.83 862.95,3228.83 854.49,3237.29 834.79,3237.29 v3(834.79,3238.14) 826.31,3229.67 826.31,3218.71 825.31,3217.71 825.31,3206.63
  Inner Layer 4 w6: 824.27,3882.11 831.31,3889.15 904.68,3889.15 909.03,3884.81 910.62,3884.81
  Inner Layer 4 w8: v3(648.08,4117.11) 650.22,4119.25 669.95,4119.25 693.95,4119.25 ; 677.93,3845.33 702.7,3870.11 742.38,3870.11 759.5,3852.99 989.76,3852.99 1030.13,3893.36 1066.27,3893.36 1066.27,3934.49 ; 678.95,4160.49 771.95,4160.49 870.95,4061.49 1008.95,4061.49 1016.95,4053.49 ; v3(736.3,2390.09) 743.3,2397.09 743.3,2490.09 ; 737.73,3944.34 733.65,3944.34 718.38,3959.61 709.95,3959.61 696.08,3973.48 696.08,3986.73 705.45,3996.11 740.72,3996.11 754.37,3982.46 1000.43,3982.46 1031.08,4013.11 1080.66,4013.11 1105.33,4013.11 v2(1114.95,4003.49) 1114.95,3936.49 v3(1112.95,3934.49) 1066.27,3934.49 ; 743.3,2503.09 743.3,2549.3 ; 743.29,2549.32 743.29,2562.93 743.3,2574.03 759.57,2590.29 759.57,2608.12 ; v3(772.45,4119.25) 693.95,4119.25 ; v3(793.08,3882.11) 824.27,3882.11 ; 910.62,3884.81 990.66,3884.81 1040.34,3934.49 1066.27,3934.49 ; v3(977.08,4010.11) 811.08,4010.11 v3(805.08,4016.11) 741.08,4080.11 v3(695.08,4080.11) 695.08,4094.11 693.95,4095.24 693.95,4119.25 ; 1004.47,3949.51 1013.04,3949.51 1037.64,3974.11 1102.33,3974.11 v3(1110.95,3965.49) ; v3(1106.25,3769.53) 1106.25,3770.27 1106.58,3770.6 v3(1106.25,3769.53)
  Inner Layer 4 w10: 730.78,3713.89 871.76,3713.89 921.24,3763.36 1073.95,3763.36 1080.11,3769.53 v3(1106.25,3769.53)
  Inner Layer 4 w12: v3(725.08,3803.11) v3(769.08,3803.11) 801.2,3803.11 822.16,3824.07 1004.43,3824.07 1031.49,3851.13 1097.26,3851.13 v3@1114.1,3834.29 ; 737.73,3944.34 751.96,3930.11 v3(849.08,3930.11) 985.06,3930.11 1004.47,3949.51 ; 759.57,2608.12 759.57,2677.02 2025.62,2677.02 2441.31,2677.02 2449.68,2685.39 v5(2518.18,2753.89) ; 2140.07,4515.64 2262.95,4392.76 2262.95,4297.15 ; 2222.4,4503.94 2224.3,4505.84 2224.3,4520.11 ; v3(2404.31,4220.09) 2403.8,4219.57 2403.8,4179.05 2415.31,4167.53 CON6401.7@2459.56,4167.53 2459.56,4171.31 2523.05,4171.31 v5@2523.05,4172.29 ; v5(2523.05,4175.08) v5@2523.05,4172.29 ; CON6401.8@2589.48,4169.5 2589.48,4172.29 v5@2523.05,4172.29
  Inner Layer 4 w14: CON6401.7@2459.56,4167.53 2474.31,4167.53 v3(2474.31,4114.09)
  Inner Layer 4 w15: v3(1106.25,3769.53) 1114.1,3777.38 v3(1114.1,3827.33) v3@1114.1,3834.29
  Inner Layer 4 w20: 81.22,3224.83 81.22,3385.74 81.22,3467.1 83.95,3469.83 v5(83.95,3510.83) ; v3(493.01,827.71) 496.86,827.71 522.31,853.16 522.31,855.09 628.95,961.73 628.95,1153.68 628.95,1566.77 629.31,1567.14 629.31,1901.46 629.31,2039.65 629.31,2156.09 v3(581.31,2204.09) ; 690.31,2199.09 701.31,2188.09 701.31,1979.21 v3(701.31,1572.65) 701.31,904.89 772.11,834.09 843.84,834.09 1477.31,834.09 1718.31,593.09 v3(1718.31,577.09) ; v3@757.31,2223.09 757.31,1906.58 757.31,1340.36 757.31,928.09 v3(772.31,913.09) 781.31,904.09 1540.9,904.09 1750.9,694.09 1763.84,694.09 1825.31,632.61 v3(1825.31,589.09)
  Inner Layer 5 w3: 1221.44,4173.97 1241.31,4173.97 ; 1764.87,3358.09 1763.58,3358.09 1752.15,3346.67 1752.15,3330.51 1761.79,3320.88 1762.37,3320.88 1762.37,3320.31 1770.9,3311.78 v3(1781.4,3311.78) ; 1765.58,3358.09 1778.69,3358.09 1779.76,3357.02 v3(1791.99,3357.02) ; v2(1817.67,3408.91) 1823.07,3403.5 1829.5,3403.5 1833.51,3399.49 1834.57,3399.49 1837.75,3396.3 1837.94,3396.3 1842.03,3392.21 1849.53,3392.21 v2(1849.53,3391.68) ; v3(2002.53,3435.36) 2007.91,3429.97 2007.91,3417.58 2008.84,3416.65 2008.84,3415.05 2008.93,3414.97 2008.93,3414.54 2009.15,3414.32 2009.15,3411.63 2010.34,3410.44 ; v3(2112.37,3495.81) 2127.9,3495.81 2133.61,3490.1 2133.87,3490.1 2134.35,3489.62 2134.46,3489.62 2134.66,3489.42 2134.72,3489.42 2134.83,3489.3 2134.96,3489.22 ; 2134.99,3489.22 2135.06,3489.15 ; 2135.09,3489.15 2135.15,3489.08 2135.24,3489.02 2135.34,3488.95 2135.46,3488.86 ; 2135.51,3488.86 2135.64,3488.73 2135.71,3488.73 2135.95,3488.48 2136.09,3488.48 2144.69,3479.88 ; 2177.36,3340.1 2178.16,3340.9 2178.54,3340.9 2184.28,3346.64 2184.28,3347.36 2185.76,3348.84 2185.76,3350.33 2187.15,3351.72 2187.15,3366.41 2183.65,3369.91 v2(2183.65,3378.59) ; 2087.65,3716.59 cw(c2087.65,3704.52) 2096.18,3713.06 ; 2087.65,3716.59 cw(c2087.65,3704.52) 2096.18,3713.06 ; 2087.65,3716.59 cw(c2087.65,3704.52) 2096.18,3713.06 ; 2087.65,3716.59 cw(c2087.65,3704.52) 2096.18,3713.06 ; 2087.65,3716.59 2075.68,3716.59 2069.15,3710.06 2069.15,3704.27 2063.85,3698.97 v2(2064.76,3698.06) 2078.73,3684.09 2094.51,3684.09 2095.01,3684.59 2174.46,3684.59 ; 2096.19,3713.05 2098.53,3710.71 ; 2098.53,3710.71 ccw(c2103.65,3715.83) 2103.65,3708.59 ; 2098.53,3710.71 ccw(c2103.65,3715.83) 2103.65,3708.59 ; 2103.65,3708.59 2167.65,3708.59 ; 2167.65,3708.59 ccw(c2167.65,3730.32) 2183.02,3714.95 ; 2167.65,3708.59 ccw(c2167.65,3730.32) 2183.02,3714.95 ; 2174.46,3684.59 ccw(c2174.46,3716.06) 2196.71,3693.81 ; 2174.46,3684.59 ccw(c2174.46,3716.06) 2196.71,3693.81 ; 2183.02,3714.95 2266.65,3798.59 2266.65,3821.59 2255.65,3832.59 2255.65,3850.15 2286.1,3880.59 2307.52,3880.59 2316.85,3871.27 ; 2196.71,3693.81 2305.65,3802.75 2305.65,3809.54 2307.32,3811.2 v3(2307.32,3828.49) 2307.32,3830.25 2320.65,3843.59 2320.65,3862.08 ; 2316.85,3871.27 cw(c2307.66,3862.08) 2320.65,3862.08 ; 2316.85,3871.27 cw(c2307.66,3862.08) 2320.65,3862.08 ; 2316.85,3871.27 cw(c2307.66,3862.08) 2320.65,3862.08 ; 2316.85,3871.27 cw(c2307.66,3862.08) 2320.65,3862.08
